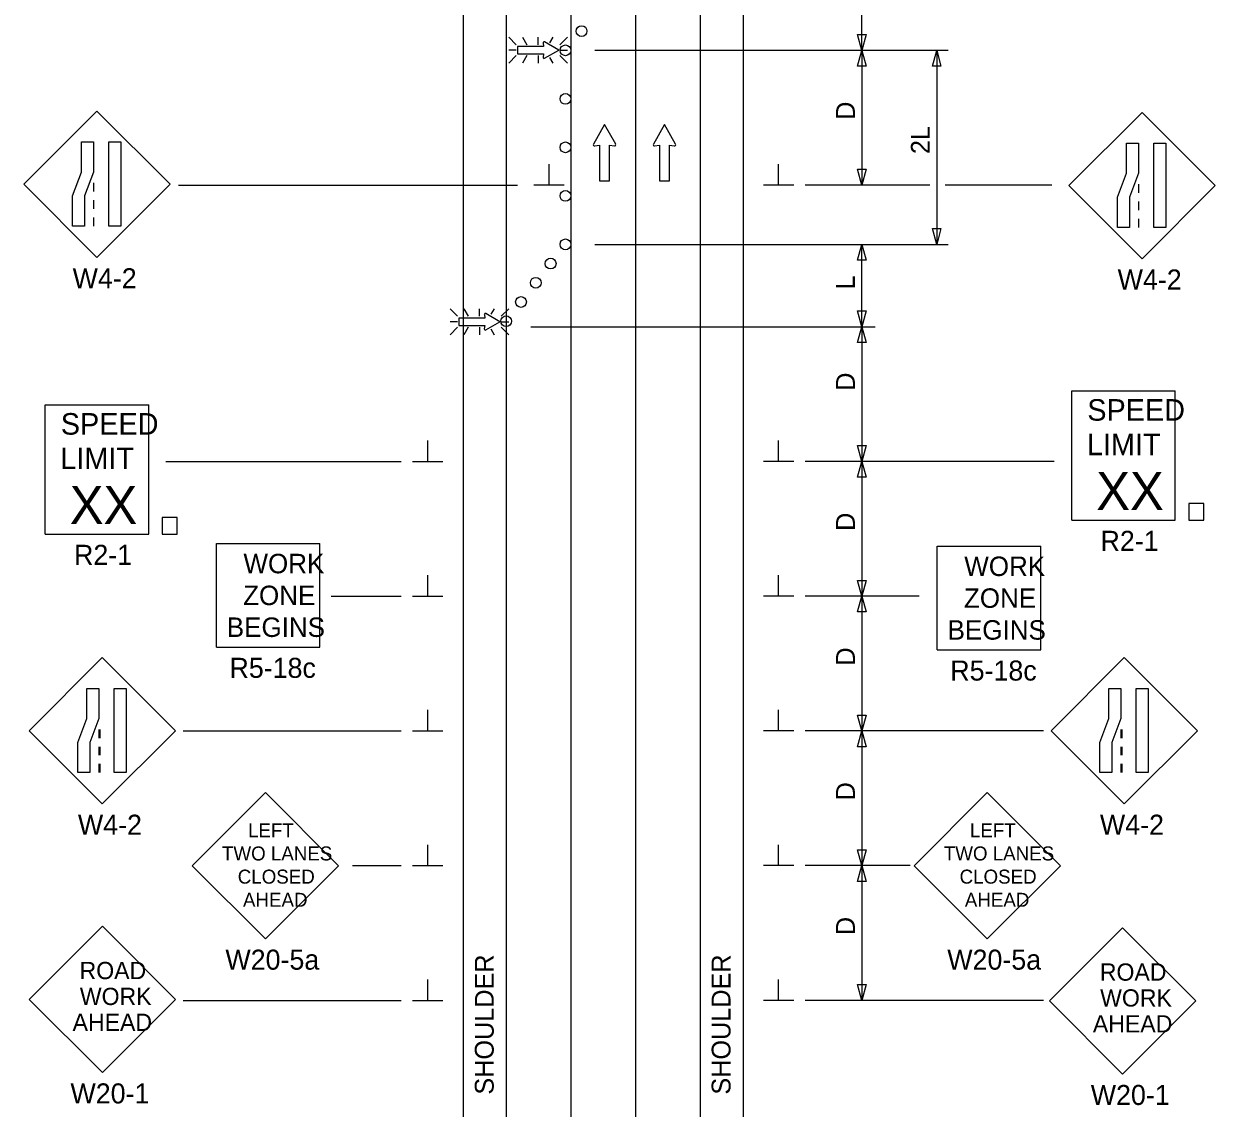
# Model space of a CAD drawing. Extents: x 16735 to 19504, y 6970 to 8243.
# Drawn here: x 17838 to 18280.2, y 7436.1 to 7838.5 of the extents above; entities that cross this region are included whole.
import ezdxf

# ---------------------------------------------------------------- set-up
doc = ezdxf.new("R2010")
doc.units = 0
for name, color, linetype in [('ALI_LEGAL_EX', 7, 'Continuous'), ('MT_SCRATCH_LEVEL_E', 7, 'Continuous'), ('PAVT_EDGE_EX', 7, 'Continuous'), ('TRAFFIC_SIGNS_PR', 7, 'Continuous'), ('TYPICAL_TEXT_DIMEN_PR', 7, 'Continuous')]:
    doc.layers.add(name, color=color, linetype=linetype)

msp = doc.modelspace()

# ---------------------------------------------------------------- linework, layer by layer
at = {"layer": 'ALI_LEGAL_EX'}
for p, q in [((18041.08, 8191.4), (18041.08, 7362.22)), ((18065.08, 8191.4), (18065.08, 7362.22)), ((18065.08, 8191.4), (18065.08, 7362.22))]:
    msp.add_line(p, q, dxfattribs=at)
for points in [[(18041.08, 7791.4), (18041.08, 7766.4)], [(18065.08, 7791.4), (18065.08, 7766.4)], [(18041.08, 7691.4), (18041.08, 7666.4)], [(18065.08, 7691.4), (18065.08, 7666.4)], [(18041.08, 7591.4), (18041.08, 7566.4)], [(18065.08, 7591.4), (18065.08, 7566.4)], [(18041.08, 7491.4), (18041.08, 7466.4)], [(18065.08, 7491.4), (18065.08, 7466.4)]]:
    msp.add_lwpolyline(points, dxfattribs=at)
at = {"layer": 'MT_SCRATCH_LEVEL_E'}
for p, q in [((18053.58, 7801.11), (18049.47, 7793.88)), ((18053.58, 7801.11), (18049.47, 7793.88)), ((18057.73, 7793.88), (18053.58, 7801.11)), ((18057.73, 7793.88), (18053.58, 7801.11)), ((18075.82, 7801.11), (18071.71, 7793.88)), ((18075.82, 7801.11), (18071.71, 7793.88)), ((18079.97, 7793.88), (18075.82, 7801.11)), ((18079.97, 7793.88), (18075.82, 7801.11)), ((18049.95, 7793.19), (18051.73, 7793.51)), ((18049.95, 7793.19), (18051.73, 7793.51)), ((18051.73, 7793.51), (18051.73, 7780.25)), ((18051.73, 7793.51), (18051.73, 7780.25)), ((18055.47, 7780.25), (18055.47, 7793.51)), ((18055.47, 7793.51), (18057.25, 7793.19)), ((18055.47, 7780.25), (18055.47, 7793.51)), ((18055.47, 7793.51), (18057.25, 7793.19)), ((18072.19, 7793.19), (18073.97, 7793.51)), ((18072.19, 7793.19), (18073.97, 7793.51)), ((18073.97, 7793.51), (18073.97, 7780.25)), ((18073.97, 7793.51), (18073.97, 7780.25)), ((18077.71, 7780.25), (18077.71, 7793.51)), ((18077.71, 7793.51), (18079.49, 7793.19)), ((18077.71, 7780.25), (18077.71, 7793.51)), ((18077.71, 7793.51), (18079.49, 7793.19)), ((18051.73, 7780.25), (18055.47, 7780.25)), ((18051.73, 7780.25), (18055.47, 7780.25)), ((18073.97, 7780.25), (18077.71, 7780.25)), ((18073.97, 7780.25), (18077.71, 7780.25))]:
    msp.add_line(p, q, dxfattribs=at)
for centre, start, end in [((18049.88, 7793.65), 150.4248, 279.9638), ((18049.88, 7793.65), 150.4248, 279.9638), ((18057.32, 7793.65), 260.0362, 29.7731), ((18057.32, 7793.65), 260.0362, 29.7731), ((18072.12, 7793.65), 150.4248, 279.9638), ((18072.12, 7793.65), 150.4248, 279.9638), ((18079.56, 7793.65), 260.0362, 29.7731), ((18079.56, 7793.65), 260.0362, 29.7731)]:
    msp.add_arc(centre, 0.463, start, end, dxfattribs=at)
at = {"layer": 'PAVT_EDGE_EX'}
for p, q in [((18001.08, 8191.4), (18001.08, 7362.22)), ((18017.08, 8191.4), (18017.08, 7362.22)), ((18017.08, 8191.4), (18017.08, 7362.22)), ((18089.08, 8191.4), (18089.08, 7362.22)), ((18105.08, 8191.4), (18105.08, 7362.22))]:
    msp.add_line(p, q, dxfattribs=at)
at = {"layer": 'TRAFFIC_SIGNS_PR'}
for p, q in [((18020.85, 7830.79), (18018.03, 7833.61)), ((18023.15, 7833.61), (18024.78, 7830.79)), ((18028.94, 7830.79), (18028.94, 7833.61)), ((18034.41, 7833.61), (18033.2, 7831.51)), ((18039.84, 7833.61), (18037.02, 7830.79)), ((18020.85, 7828.76), (18018.03, 7828.76)), ((18037.02, 7828.76), (18039.84, 7828.76)), ((18020.85, 7826.72), (18018.03, 7823.9)), ((18024.8, 7826.72), (18023.17, 7823.9)), ((18028.94, 7826.72), (18028.94, 7823.9)), ((18033.12, 7826.09), (18034.38, 7823.9)), ((18039.84, 7823.9), (18037.02, 7826.72)), ((17865.2, 7806.13), (17838.05, 7778.97)), ((17892.35, 7778.97), (17865.2, 7806.13)), ((18253.1, 7805.66), (18225.94, 7778.51)), ((18280.25, 7778.51), (18253.1, 7805.66)), ((17838.05, 7778.97), (17865.2, 7751.82)), ((17863.95, 7779.47), (17863.95, 7776.27)), ((17865.2, 7751.82), (17892.35, 7778.97)), ((18225.94, 7778.51), (18253.1, 7751.36)), ((18251.85, 7779), (18251.85, 7775.8)), ((18253.1, 7751.36), (18280.25, 7778.51)), ((17863.95, 7773.07), (17863.95, 7769.87)), ((18251.85, 7772.6), (18251.85, 7769.4)), ((17863.95, 7766.67), (17863.95, 7763.47)), ((18251.85, 7766.2), (18251.85, 7763)), ((17999.06, 7729.99), (17996.24, 7732.81)), ((18001.36, 7732.81), (18002.99, 7729.99)), ((18007.15, 7729.99), (18007.15, 7732.81)), ((18012.62, 7732.81), (18011.41, 7730.72)), ((18018.05, 7732.81), (18015.23, 7729.99)), ((17999.06, 7727.96), (17996.24, 7727.96)), ((17999.06, 7725.92), (17996.24, 7723.1)), ((18003.01, 7725.92), (18001.39, 7723.1)), ((18007.15, 7725.92), (18007.15, 7723.1)), ((18011.33, 7725.29), (18012.59, 7723.1)), ((18015.23, 7727.96), (18018.05, 7727.96)), ((18018.05, 7723.11), (18015.23, 7725.92)), ((18227.01, 7702.38), (18265.41, 7702.38)), ((18227.01, 7654.38), (18227.01, 7702.38)), ((18265.41, 7654.38), (18265.41, 7702.38)), ((17846, 7697.19), (17884.4, 7697.19)), ((17846, 7649.19), (17846, 7697.19)), ((17884.4, 7649.19), (17884.4, 7697.19)), ((18227.01, 7654.38), (18265.41, 7654.38)), ((17846, 7649.19), (17884.4, 7649.19)), ((17909.57, 7607.25), (17909.57, 7645.65)), ((17909.57, 7645.65), (17947.97, 7645.65)), ((17947.97, 7607.25), (17947.97, 7645.65)), ((18177.12, 7606.24), (18177.12, 7644.64)), ((18177.12, 7644.64), (18215.52, 7644.64)), ((18215.52, 7606.24), (18215.52, 7644.64)), ((17909.57, 7607.25), (17947.97, 7607.25)), ((18177.12, 7606.24), (18215.52, 7606.24)), ((17867.16, 7603.34), (17840.01, 7576.18)), ((17894.31, 7576.18), (17867.16, 7603.34)), ((18246.51, 7603.34), (18219.36, 7576.18)), ((18273.66, 7576.18), (18246.51, 7603.34)), ((17840.01, 7576.18), (17867.16, 7549.03)), ((17865.91, 7576.67), (17865.91, 7573.47)), ((17866.31, 7576.67), (17866.31, 7573.47)), ((17867.16, 7549.03), (17894.31, 7576.18)), ((18219.36, 7576.18), (18246.51, 7549.03)), ((18245.26, 7576.67), (18245.26, 7573.47)), ((18245.66, 7576.67), (18245.66, 7573.47)), ((18246.51, 7549.03), (18273.66, 7576.18)), ((17865.91, 7570.27), (17865.91, 7567.07)), ((17866.31, 7570.27), (17866.31, 7567.07)), ((18245.26, 7570.27), (18245.26, 7567.07)), ((18245.66, 7570.27), (18245.66, 7567.07)), ((17865.91, 7563.87), (17865.91, 7560.67)), ((17866.31, 7563.87), (17866.31, 7560.67)), ((18245.26, 7563.87), (18245.26, 7560.67)), ((18245.66, 7563.87), (18245.66, 7560.67)), ((17927.74, 7553.26), (17900.58, 7526.11)), ((17954.89, 7526.11), (17927.74, 7553.26)), ((18195.67, 7553.26), (18168.52, 7526.11)), ((18222.83, 7526.11), (18195.67, 7553.26)), ((17900.58, 7526.11), (17927.74, 7498.95)), ((17927.74, 7498.95), (17954.89, 7526.11)), ((18168.52, 7526.11), (18195.67, 7498.95)), ((18195.67, 7498.95), (18222.83, 7526.11)), ((17867.19, 7503.62), (17840.04, 7476.47)), ((17894.35, 7476.47), (17867.19, 7503.62)), ((18245.9, 7503.05), (18218.75, 7475.9)), ((18273.06, 7475.9), (18245.9, 7503.05)), ((17840.04, 7476.47), (17867.19, 7449.31)), ((17867.19, 7449.31), (17894.35, 7476.47)), ((18218.75, 7475.9), (18245.9, 7448.74)), ((18245.9, 7448.74), (18273.06, 7475.9))]:
    msp.add_line(p, q, dxfattribs=at)
for points in [[(18030.76, 7831.44), (18030.99, 7830.14), (18021.27, 7830.14), (18021.27, 7827.4), (18030.99, 7827.4), (18030.76, 7826.09)], [(18031.26, 7825.74), (18036.57, 7828.76), (18031.26, 7831.8)], [(18008.98, 7730.64), (18009.21, 7729.34), (17999.48, 7729.34), (17999.48, 7726.6), (18009.21, 7726.6), (18008.97, 7725.3)], [(18009.48, 7724.94), (18014.78, 7727.96), (18009.48, 7731)]]:
    msp.add_lwpolyline(points, dxfattribs=at)
for points in [[(17863.95, 7794.71), (17863.95, 7783.53), (17860.61, 7774.65), (17860.61, 7763.47), (17856.12, 7763.47), (17856.12, 7774.65), (17859.46, 7783.53), (17859.46, 7794.71)], [(17874.09, 7794.71), (17874.09, 7763.47), (17869.6, 7763.47), (17869.6, 7794.71)], [(18251.85, 7794.25), (18251.85, 7783.06), (18248.5, 7774.18), (18248.5, 7763), (18244.01, 7763), (18244.01, 7774.18), (18247.35, 7783.06), (18247.35, 7794.25)], [(18261.98, 7794.25), (18261.98, 7763), (18257.49, 7763), (18257.49, 7794.25)], [(18270.43, 7654.38), (18276.02, 7654.38), (18276.02, 7660.55), (18270.43, 7660.55)], [(17889.42, 7649.19), (17895.01, 7649.19), (17895.01, 7655.37), (17889.42, 7655.37)], [(17865.91, 7591.92), (17865.91, 7580.74), (17862.57, 7571.86), (17862.57, 7560.67), (17858.07, 7560.67), (17858.07, 7571.86), (17861.42, 7580.74), (17861.42, 7591.92)], [(17876.05, 7591.92), (17876.05, 7560.67), (17871.55, 7560.67), (17871.55, 7591.92)], [(18245.26, 7591.92), (18245.26, 7580.74), (18241.92, 7571.86), (18241.92, 7560.67), (18237.42, 7560.67), (18237.42, 7571.86), (18240.77, 7580.74), (18240.77, 7591.92)], [(18255.4, 7591.92), (18255.4, 7560.67), (18250.9, 7560.67), (18250.9, 7591.92)]]:
    msp.add_lwpolyline(points, close=True, dxfattribs=at)
for centre in [(18045.08, 7835.82), (18039.08, 7828.69), (18039.08, 7810.68), (18039.08, 7792.68), (18039.08, 7774.68), (18039.08, 7756.68), (18033.58, 7749.55), (18028.08, 7742.43), (18022.59, 7735.3), (18017.09, 7728.17)]:
    msp.add_circle(centre, 2, dxfattribs=at)
for centre, start, end in [((18031.1, 7831.5), 61.4833, 189.9593), ((18031.1, 7826.04), 170.7308, 298.8916), ((18009.31, 7730.7), 61.4833, 189.9593), ((18009.31, 7725.24), 170.7308, 298.8916)]:
    msp.add_arc(centre, 0.341, start, end, dxfattribs=at)
at = {"layer": 'TYPICAL_TEXT_DIMEN_PR'}
for p, q in [((18149.08, 7828.68), (18149.08, 7859.25)), ((18149.08, 7828.68), (18147.51, 7834.55)), ((18147.51, 7834.55), (18149.08, 7834.55)), ((18149.08, 7834.55), (18150.65, 7834.55)), ((18150.65, 7834.55), (18149.08, 7828.68)), ((18181.12, 7828.68), (18049.98, 7828.68)), ((18147.51, 7822.82), (18149.08, 7828.68)), ((18149.08, 7828.68), (18149.08, 7778.68)), ((18149.08, 7828.68), (18150.65, 7822.82)), ((18175.31, 7822.82), (18176.88, 7828.68)), ((18176.88, 7828.68), (18178.45, 7822.82)), ((18176.88, 7828.68), (18176.88, 7756.68)), ((18149.08, 7822.82), (18147.51, 7822.82)), ((18150.65, 7822.82), (18149.08, 7822.82)), ((18176.88, 7822.82), (18175.31, 7822.82)), ((18178.45, 7822.82), (18176.88, 7822.82)), ((18033, 7778.68), (18033, 7786.47)), ((18118.2, 7778.68), (18118.2, 7786.47)), ((18149.08, 7778.68), (18147.51, 7784.55)), ((18147.51, 7784.55), (18149.08, 7784.55)), ((18149.08, 7784.55), (18150.65, 7784.55)), ((18150.65, 7784.55), (18149.08, 7778.68)), ((18176.88, 7783.55), (18176.88, 7779.78)), ((17895.52, 7778.68), (18021.28, 7778.68)), ((18038.63, 7778.68), (18027.38, 7778.68)), ((18123.83, 7778.68), (18112.58, 7778.68)), ((18174.37, 7778.68), (18128.08, 7778.68)), ((18219.63, 7778.68), (18179.98, 7778.68)), ((18176.88, 7756.68), (18175.31, 7762.55)), ((18175.31, 7762.55), (18176.88, 7762.55)), ((18176.88, 7762.55), (18178.45, 7762.55)), ((18178.45, 7762.55), (18176.88, 7756.68)), ((18049.98, 7756.68), (18181.12, 7756.68)), ((18147.51, 7750.82), (18149.08, 7756.68)), ((18149.08, 7726.12), (18149.08, 7756.68)), ((18149.08, 7756.68), (18150.65, 7750.82)), ((18149.08, 7750.82), (18147.51, 7750.82)), ((18150.65, 7750.82), (18149.08, 7750.82)), ((18149.08, 7726.12), (18147.51, 7731.98)), ((18147.51, 7731.98), (18149.08, 7731.98)), ((18149.08, 7731.98), (18150.65, 7731.98)), ((18150.65, 7731.98), (18149.08, 7726.12)), ((18026.24, 7726.12), (18154.08, 7726.12)), ((18147.51, 7720.26), (18149.08, 7726.12)), ((18147.51, 7720.26), (18149.08, 7726.12)), ((18149.08, 7726.12), (18149.08, 7676.12)), ((18149.08, 7726.12), (18150.65, 7720.26)), ((18149.08, 7726.12), (18150.65, 7720.26)), ((18149.08, 7720.26), (18147.51, 7720.26)), ((18149.08, 7720.26), (18147.51, 7720.26)), ((18150.65, 7720.26), (18149.08, 7720.26)), ((18150.65, 7720.26), (18149.08, 7720.26)), ((17987.95, 7676.12), (17987.95, 7683.9)), ((18118.2, 7676.12), (18118.2, 7683.9)), ((18149.08, 7676.12), (18147.51, 7681.98)), ((18147.51, 7681.98), (18149.08, 7681.98)), ((18149.08, 7676.12), (18147.51, 7681.98)), ((18147.51, 7681.98), (18149.08, 7681.98)), ((18149.08, 7681.98), (18150.65, 7681.98)), ((18150.65, 7681.98), (18149.08, 7676.12)), ((18149.08, 7681.98), (18150.65, 7681.98)), ((18150.65, 7681.98), (18149.08, 7676.12)), ((17890.75, 7676.12), (17978.08, 7676.12)), ((17982.33, 7676.12), (17993.58, 7676.12)), ((18123.83, 7676.12), (18112.58, 7676.12)), ((18220.52, 7676.12), (18128.08, 7676.12)), ((18147.51, 7670.26), (18149.08, 7676.12)), ((18147.51, 7670.26), (18149.08, 7676.12)), ((18149.08, 7676.12), (18149.08, 7626.12)), ((18149.08, 7676.12), (18150.65, 7670.26)), ((18149.08, 7676.12), (18150.65, 7670.26)), ((18149.08, 7670.26), (18147.51, 7670.26)), ((18149.08, 7670.26), (18147.51, 7670.26)), ((18150.65, 7670.26), (18149.08, 7670.26)), ((18150.65, 7670.26), (18149.08, 7670.26)), ((17987.95, 7626.12), (17987.95, 7633.9)), ((18118.2, 7626.12), (18118.2, 7633.9)), ((18149.08, 7626.12), (18147.51, 7631.98)), ((18147.51, 7631.98), (18149.08, 7631.98)), ((18149.08, 7626.12), (18147.51, 7631.98)), ((18147.51, 7631.98), (18149.08, 7631.98)), ((18149.08, 7631.98), (18150.65, 7631.98)), ((18150.65, 7631.98), (18149.08, 7626.12)), ((18149.08, 7631.98), (18150.65, 7631.98)), ((18150.65, 7631.98), (18149.08, 7626.12)), ((17952.08, 7626.12), (17978.08, 7626.12)), ((17982.33, 7626.12), (17993.58, 7626.12)), ((18123.83, 7626.12), (18112.58, 7626.12)), ((18170.34, 7626.12), (18128.08, 7626.12)), ((18147.51, 7620.26), (18149.08, 7626.12)), ((18149.08, 7626.12), (18150.65, 7620.26)), ((18149.08, 7626.12), (18149.08, 7576.12)), ((18149.08, 7620.26), (18147.51, 7620.26)), ((18150.65, 7620.26), (18149.08, 7620.26)), ((17987.95, 7576.12), (17987.95, 7583.9)), ((18118.2, 7576.12), (18118.2, 7583.9)), ((18149.08, 7576.12), (18147.51, 7581.98)), ((18147.51, 7581.98), (18149.08, 7581.98)), ((18149.08, 7576.12), (18147.51, 7581.98)), ((18147.51, 7581.98), (18149.08, 7581.98)), ((18149.08, 7581.98), (18150.65, 7581.98)), ((18150.65, 7581.98), (18149.08, 7576.12)), ((18149.08, 7581.98), (18150.65, 7581.98)), ((18150.65, 7581.98), (18149.08, 7576.12)), ((17897.25, 7576.12), (17978.08, 7576.12)), ((17982.33, 7576.12), (17993.58, 7576.12)), ((18123.83, 7576.12), (18112.58, 7576.12)), ((18216.54, 7576.12), (18128.08, 7576.12)), ((18147.51, 7570.26), (18149.08, 7576.12)), ((18147.51, 7570.26), (18149.08, 7576.12)), ((18149.08, 7576.12), (18149.08, 7526.12)), ((18149.08, 7576.12), (18150.65, 7570.26)), ((18149.08, 7576.12), (18150.65, 7570.26)), ((18149.08, 7570.26), (18147.51, 7570.26)), ((18149.08, 7570.26), (18147.51, 7570.26)), ((18150.65, 7570.26), (18149.08, 7570.26)), ((18150.65, 7570.26), (18149.08, 7570.26)), ((17987.95, 7526.12), (17987.95, 7533.9)), ((18118.2, 7526.12), (18118.2, 7533.9)), ((18149.08, 7526.12), (18147.51, 7531.98)), ((18147.51, 7531.98), (18149.08, 7531.98)), ((18149.08, 7526.12), (18147.51, 7531.98)), ((18147.51, 7531.98), (18149.08, 7531.98)), ((18149.08, 7531.98), (18150.65, 7531.98)), ((18150.65, 7531.98), (18149.08, 7526.12)), ((18149.08, 7531.98), (18150.65, 7531.98)), ((18150.65, 7531.98), (18149.08, 7526.12)), ((17960.02, 7526.12), (17978.08, 7526.12)), ((17982.33, 7526.12), (17993.58, 7526.12)), ((18123.83, 7526.12), (18112.58, 7526.12)), ((18167.08, 7526.12), (18128.08, 7526.12)), ((18147.51, 7520.26), (18149.08, 7526.12)), ((18149.08, 7526.12), (18149.08, 7476.12)), ((18149.08, 7526.12), (18150.65, 7520.26)), ((18149.08, 7520.26), (18147.51, 7520.26)), ((18150.65, 7520.26), (18149.08, 7520.26)), ((17987.95, 7476.12), (17987.95, 7483.9)), ((18118.2, 7476.12), (18118.2, 7483.9)), ((18149.08, 7476.12), (18147.51, 7481.98)), ((18147.51, 7481.98), (18149.08, 7481.98)), ((18149.08, 7481.98), (18150.65, 7481.98)), ((18150.65, 7481.98), (18149.08, 7476.12)), ((17897.25, 7476.12), (17978.08, 7476.12)), ((17982.33, 7476.12), (17993.58, 7476.12)), ((18123.83, 7476.12), (18112.58, 7476.12)), ((18216.54, 7476.12), (18128.08, 7476.12))]:
    msp.add_line(p, q, dxfattribs=at)

# ---------------------------------------------------------------- texts
at = {"layer": 'TRAFFIC_SIGNS_PR'}
for s, height, p in [('W4-2', 7.44, (17856.16, 7740.38)), ('W4-2', 7.44, (18244.05, 7739.92)), ('SPEED', 8, (18232.78, 7691.24)), ('SPEED', 8, (17851.77, 7686.06)), ('LIMIT', 8, (18232.62, 7678.44)), ('LIMIT', 8, (17851.61, 7673.26)), ('XX', 14.031, (18236.12, 7658.14)), ('XX', 14.031, (17855.11, 7652.95)), ('R2-1', 7.44, (18237.69, 7642.94)), ('R2-1', 7.44, (17856.68, 7637.75)), ('WORK', 7.217, (17919.57, 7634.62)), ('WORK', 7.217, (18187.12, 7633.61)), ('ZONE', 7.217, (17919.45, 7622.81)), ('ZONE', 7.217, (18187, 7621.8)), ('BEGINS', 7.217, (17913.38, 7611)), ('BEGINS', 7.217, (18180.93, 7609.99)), ('R5-18c', 7.44, (17914.38, 7595.81)), ('R5-18c', 7.44, (18181.93, 7594.8)), ('W4-2', 7.44, (17858.12, 7537.59)), ('W4-2', 7.44, (18237.47, 7537.59)), ('LEFT', 5.2, (17921.27, 7536.64)), ('LEFT', 5.2, (18189.21, 7536.64)), ('TWO LANES', 5.2, (17911.6, 7528.04)), ('TWO LANES', 5.2, (18179.53, 7528.04)), ('CLOSED', 5.2, (17917.45, 7519.44)), ('CLOSED', 5.2, (18185.38, 7519.44)), ('AHEAD', 5.2, (17919.39, 7510.84)), ('AHEAD', 5.2, (18187.33, 7510.84)), ('W20-5a', 7.44, (17912.87, 7487.51)), ('W20-5a', 7.44, (18180.81, 7487.51)), ('ROAD', 6.4, (17858.74, 7484)), ('ROAD', 6.4, (18237.44, 7483.43)), ('WORK', 6.4, (17858.84, 7474.4)), ('WORK', 6.4, (18237.55, 7473.83)), ('AHEAD', 6.4, (17856.15, 7464.8)), ('AHEAD', 6.4, (18234.86, 7464.23)), ('W20-1', 7.44, (17855.36, 7437.87)), ('W20-1', 7.44, (18234.07, 7437.3))]:
    msp.add_text(s, height=height, dxfattribs=at).set_placement(p)
at = {"layer": 'TYPICAL_TEXT_DIMEN_PR'}
for s, p in [('D', (18146.52, 7802.9)), ('2L', (18174.33, 7790.19)), ('L', (18146.52, 7739.98)), ('D', (18146.52, 7702.35)), ('D', (18146.52, 7650.34)), ('D', (18146.52, 7600.34)), ('D', (18146.52, 7550.34)), ('D', (18146.52, 7500.34)), ('SHOULDER', (18012.46, 7441.15)), ('SHOULDER', (18100.36, 7441.15))]:
    msp.add_text(s, height=7, rotation=90, dxfattribs=at).set_placement(p)

doc.saveas('drawing.dxf')
